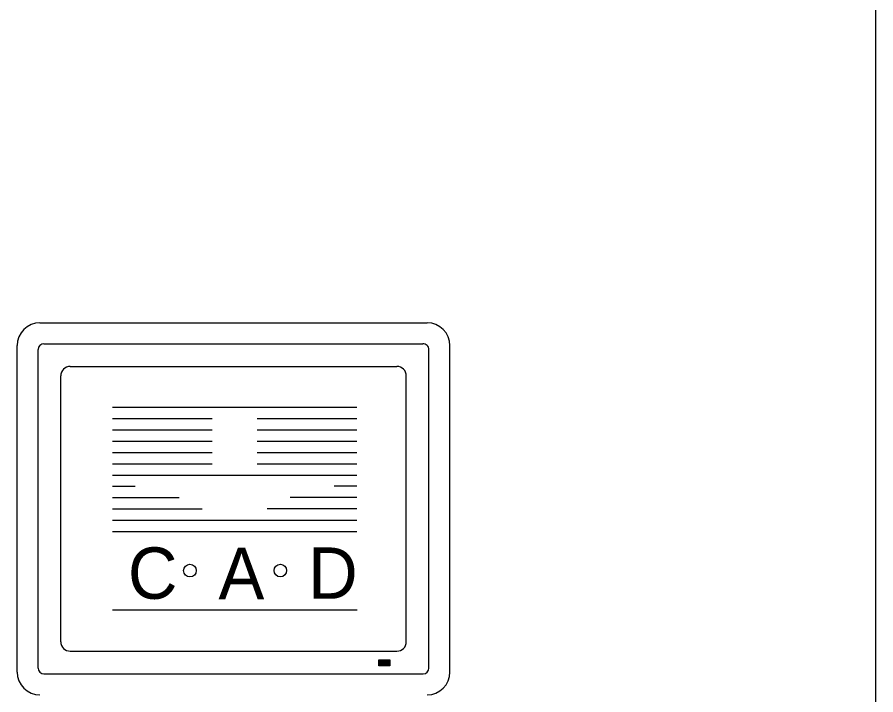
# Model space of a CAD drawing. Extents: x 22369.6 to 22413.6, y 22369.6 to 22403.6.
# Drawn here: x 22407.881 to 22410.37, y 22371.471 to 22373.434 of the extents above; entities that cross this region are included whole.
import ezdxf

# ---------------------------------------------------------------- set-up
doc = ezdxf.new("R2010")
doc.units = 0
for name, color, linetype in [('Level 2', 7, 'Continuous'), ('Level 3', 7, 'Continuous'), ('Level 5', 7, 'Continuous'), ('Level 9', 7, 'Continuous')]:
    doc.layers.add(name, color=color, linetype=linetype)

msp = doc.modelspace()

# ---------------------------------------------------------------- linework, layer by layer
at = {"layer": 'Level 2'}
for p, q in [((22408.0353, 22372.4225), (22408.9816, 22372.4225)), ((22408.0078, 22371.6252), (22408.0078, 22372.395)), ((22409.0091, 22371.6252), (22409.0091, 22372.395)), ((22408.0353, 22371.5977), (22408.9816, 22371.5977)), ((22408.9297, 22371.5718), (22408.9611, 22371.5718)), ((22408.9297, 22371.5709), (22408.9611, 22371.5709)), ((22408.9297, 22371.5699), (22408.9611, 22371.5699)), ((22408.9297, 22371.5688), (22408.9611, 22371.5688)), ((22408.9297, 22371.5678), (22408.9611, 22371.5678)), ((22408.9297, 22371.5669), (22408.9611, 22371.5669)), ((22408.9297, 22371.5659), (22408.9611, 22371.5659)), ((22408.9297, 22371.5649), (22408.9611, 22371.5649)), ((22408.9297, 22371.5639), (22408.9611, 22371.5639)), ((22408.9297, 22371.5629), (22408.9611, 22371.5629)), ((22408.9297, 22371.5619), (22408.9611, 22371.5619)), ((22408.9297, 22371.5609), (22408.9611, 22371.5609)), ((22408.9297, 22371.56), (22408.9611, 22371.56)), ((22408.9297, 22371.5589), (22408.9611, 22371.5589)), ((22408.9297, 22371.5579), (22408.9611, 22371.5579)), ((22408.9297, 22371.557), (22408.9611, 22371.557)), ((22408.9297, 22371.556), (22408.9611, 22371.556))]:
    msp.add_line(p, q, dxfattribs=at)
msp.add_lwpolyline([(22408.9297, 22371.5725), (22408.9611, 22371.5725), (22408.9611, 22371.5552), (22408.9297, 22371.5552)], close=True, dxfattribs=at)
for centre in [(22408.3819, 22371.8312), (22408.644, 22371.8314)]:
    msp.add_circle(centre, 0.0183, dxfattribs=at)
for centre, start, end in [((22408.0353, 22372.395), 90, 180), ((22408.9815, 22372.395), 0, 90), ((22408.0353, 22371.6252), 180, 270), ((22408.9815, 22371.6252), 270, 0)]:
    msp.add_arc(centre, 0.0275, start, end, dxfattribs=at)
at = {"layer": 'Level 3'}
for p, q in [((22407.9474, 22372.5489), (22409.0694, 22372.5489)), ((22407.8814, 22371.5373), (22407.8814, 22372.4829)), ((22407.9423, 22371.5488), (22407.9423, 22372.4715)), ((22407.9588, 22372.488), (22409.0569, 22372.488)), ((22409.0746, 22371.5488), (22409.0746, 22372.4715)), ((22409.1354, 22371.5373), (22409.1354, 22372.4829)), ((22407.9588, 22371.5323), (22409.0569, 22371.5323))]:
    msp.add_line(p, q, dxfattribs=at)
for centre, radius, start, end in [((22407.9474, 22372.4829), 0.066, 90, 180), ((22409.0694, 22372.4829), 0.066, 0, 90), ((22407.9588, 22372.4715), 0.0165, 90, 180), ((22409.058, 22372.4715), 0.0165, 0, 93.8704), ((22407.9588, 22371.5487), 0.0165, 180, 270), ((22409.058, 22371.5487), 0.0165, 270, 0), ((22407.9474, 22371.5373), 0.066, 180, 270), ((22409.0694, 22371.5373), 0.066, 270, 0)]:
    msp.add_arc(centre, radius, start, end, dxfattribs=at)
at = {"layer": 'Level 5'}
for p, q in [((22408.1579, 22372.3042), (22408.8654, 22372.3042)), ((22408.1579, 22372.2714), (22408.4463, 22372.2714)), ((22408.5769, 22372.2714), (22408.8654, 22372.2714)), ((22408.1579, 22372.2388), (22408.4463, 22372.2388)), ((22408.5769, 22372.2388), (22408.8654, 22372.2388)), ((22408.1579, 22372.2062), (22408.4463, 22372.2062)), ((22408.5769, 22372.2062), (22408.8654, 22372.2062)), ((22408.1579, 22372.1734), (22408.4463, 22372.1734)), ((22408.5769, 22372.1734), (22408.8654, 22372.1734)), ((22408.1579, 22372.1407), (22408.4463, 22372.1407)), ((22408.5769, 22372.1407), (22408.8654, 22372.1407)), ((22408.1579, 22372.1079), (22408.8654, 22372.1079)), ((22408.1579, 22372.0754), (22408.2233, 22372.0754)), ((22408.8653, 22372.0754), (22408.7999, 22372.0754)), ((22408.1579, 22372.0427), (22408.3507, 22372.0427)), ((22408.8653, 22372.0427), (22408.6726, 22372.0427)), ((22408.1579, 22372.01), (22408.4177, 22372.01)), ((22408.8653, 22372.01), (22408.6056, 22372.01)), ((22408.1579, 22371.9773), (22408.8654, 22371.9773)), ((22408.1579, 22371.9445), (22408.8654, 22371.9445)), ((22408.1579, 22371.7177), (22408.8667, 22371.7177))]:
    msp.add_line(p, q, dxfattribs=at)
at = {"layer": 'Level 9'}
msp.add_lwpolyline([(22410.3697, 22370.1253), (22410.3697, 22403.1253)], dxfattribs=at)

# ---------------------------------------------------------------- texts
at = {"layer": 'Level 5'}
for s, p in [('C', (22408.2023, 22371.7495)), ('A', (22408.4648, 22371.7483)), ('D', (22408.7246, 22371.7495))]:
    msp.add_text(s, height=0.1488, dxfattribs=at).set_placement(p)

doc.saveas('drawing.dxf')
